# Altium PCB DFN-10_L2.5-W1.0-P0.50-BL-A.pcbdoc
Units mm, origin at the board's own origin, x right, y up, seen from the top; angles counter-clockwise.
Board outline 15.5 x 14.43 mm, 2 copper layers (Top Layer, Bottom Layer), stack 0 mm thick; 1 components, 0 nets, 10 pads, 0 vias.
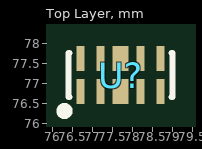
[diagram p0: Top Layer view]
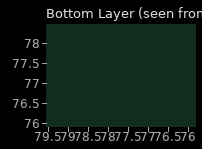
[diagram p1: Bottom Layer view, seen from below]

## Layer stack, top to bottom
Top Layer: signal copper (thickness not stored)
Bottom Layer: signal copper (thickness not stored)

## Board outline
85.35,69.85 69.85,69.85 69.85,84.278 85.35,84.278

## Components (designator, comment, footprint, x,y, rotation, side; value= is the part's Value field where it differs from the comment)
U? "" DFN-10_L2.5-W1.0-P0.50-BL-A 77.7,77.2 r0 top

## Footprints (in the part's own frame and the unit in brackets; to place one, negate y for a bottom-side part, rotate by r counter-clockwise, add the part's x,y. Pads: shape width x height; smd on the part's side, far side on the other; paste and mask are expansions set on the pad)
DFN-10_L2.5-W1.0-P0.50-BL-A [mm]
  rect 0.2x0.633 smd: 1(-1,-0.411) 2(-0.5,-0.411) 4(0.5,-0.411) 5(1,-0.411) 6(1,0.411) 7(0.5,0.411) 9(-0.5,0.411) 10(-1,0.411)
  rect 0.4x0.633 smd: 3(0,-0.411) 8(0,0.411)
  silkscreen extent -1.5,-1 1.3,0.55

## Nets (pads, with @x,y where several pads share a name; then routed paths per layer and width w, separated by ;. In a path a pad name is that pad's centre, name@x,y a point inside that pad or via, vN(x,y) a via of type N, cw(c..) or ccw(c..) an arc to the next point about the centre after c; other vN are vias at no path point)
pads on no net: U?.1 U?.2 U?.3 U?.4 U?.5 U?.6 U?.7 U?.8 U?.9 U?.10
